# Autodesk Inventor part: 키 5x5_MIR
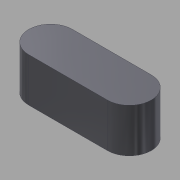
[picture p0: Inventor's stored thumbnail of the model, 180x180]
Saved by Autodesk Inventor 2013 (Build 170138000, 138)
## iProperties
Created: 2014-10
Part Number: 키 5x5_MIR
Material: 강철, 연강
Document SubType Name: Modeling
Designer: Administrator
Mass: 2.54015 g
Surface Area: 2.9781 cm^2
Volume: 0.323175 cm^3
Density: 7.86 g/cm^3
Author: SeoGD™ [www.esajin.kr]
Revision Number: 1
d0: 5.000 mm
d1: 14.000 mm
d2: 5.000 mm
d3: 0.00 deg
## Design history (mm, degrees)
derived "키 5x5.ipt"
  sketch "스케치1"
    geometry: L1 (4.5, -2.5)-(-4.5, -2.5) reference; L2 (-4.5, 2.5)-(4.5, 2.5) reference; A1 r 2.5 centre (-4.5, 0) between (-4.5, 2.5) and (-4.5, -2.5) reference; A2 r 2.5 centre (4.5, 0) between (4.5, -2.5) and (4.5, 2.5) reference; 2 further points
feature "솔리드1::키 5x5.ipt"
tag "피쳐 태그1"
node "솔리드1"
other parameters: "d0" = 10, "d0_1" = 5, "d1" = 14, "d2" = 5, "d3" = 0 deg
